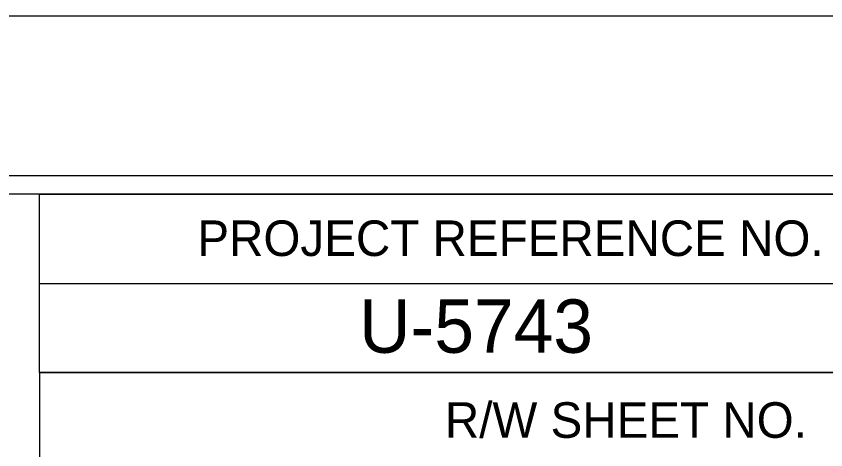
# Model space of a CAD drawing. Extents: x 1901670 to 1902225, y 193498 to 194278.
# Drawn here: x 1902112.21 to 1902123.59, y 194261.92 to 194268.01 of the extents above; entities that cross this region are included whole.
import ezdxf

# ---------------------------------------------------------------- set-up
doc = ezdxf.new("R2010")
doc.units = 0
for name, color, linetype in [('Sheet Border Standard 30in CELL', 7, 'Continuous'), ('Sheet Cutting Line CELL', 7, 'Continuous'), ('Sheet Data Field CELL', 7, 'Continuous'), ('Sheet Plot Border Inside CELL', 7, 'Continuous'), ('Sheet Plot Border Outside CELL', 7, 'Continuous')]:
    doc.layers.add(name, color=color, linetype=linetype)

msp = doc.modelspace()

# ---------------------------------------------------------------- linework, layer by layer
at = {"layer": 'Sheet Border Standard 30in CELL'}
for p, q in [((1902112.539, 194264.259), (1902132.544, 194264.259)), ((1902112.539, 194263.009), (1902132.544, 194263.009)), ((1902112.539, 194263.009), (1902112.539, 194261.759)), ((1902112.539, 194263.009), (1902132.544, 194263.009))]:
    msp.add_line(p, q, dxfattribs=at)
for points in [[(1902132.544, 194265.514), (1901982.544, 194265.514), (1901982.544, 194160.514), (1902132.544, 194160.514)], [(1902112.539, 194265.514), (1902132.544, 194265.514), (1902132.544, 194263.009), (1902112.539, 194263.009)]]:
    msp.add_lwpolyline(points, close=True, dxfattribs=at)
at = {"layer": 'Sheet Cutting Line CELL'}
msp.add_line((1902134.244, 194268.014), (1901965.844, 194268.014), dxfattribs=at)
at = {"layer": 'Sheet Plot Border Inside CELL'}
msp.add_lwpolyline([(1902133.794, 194265.769), (1901967.144, 194265.769), (1901967.144, 194160.259), (1902133.794, 194160.259)], close=True, dxfattribs=at)
at = {"layer": 'Sheet Plot Border Outside CELL'}
msp.add_lwpolyline([(1902134.244, 194268.014), (1901965.844, 194268.014), (1901965.844, 194158.014), (1902134.244, 194158.014)], close=True, dxfattribs=at)

# ---------------------------------------------------------------- texts
at = {"layer": 'Sheet Border Standard 30in CELL'}
for s, p in [('PROJECT REFERENCE NO.', (1902114.759, 194264.644)), ('R/W SHEET NO.', (1902118.239, 194262.089))]:
    msp.add_text(s, height=0.50001, dxfattribs=at).set_placement(p)
at = {"layer": 'Sheet Data Field CELL'}
msp.add_text('U-5743', height=0.75, dxfattribs=at).set_placement((1902117.032, 194263.284))

doc.saveas('drawing.dxf')
